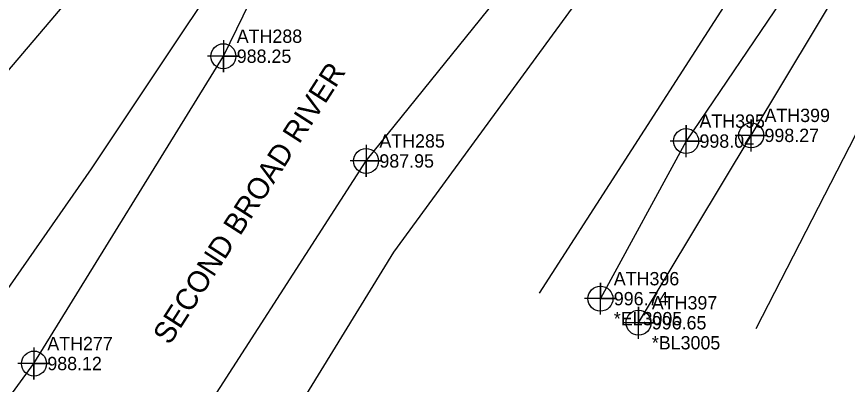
# Model space of a CAD drawing. Extents: x 1116345 to 1117546, y 660629 to 661859.
# Drawn here: x 1116970 to 1117125.8, y 661227.1 to 661296.1 of the extents above; entities that cross this region are included whole.
import ezdxf

# ---------------------------------------------------------------- set-up
doc = ezdxf.new("R2010")
doc.units = 0
for name, color, linetype in [('Exist DTM Drainline Cogo Elevation', 7, 'Continuous'), ('Exist DTM Drainline Cogo Number', 7, 'Continuous'), ('Exist DTM Drainline Cogo Point CELL', 7, 'Continuous'), ('Exist DTM Drainline Text', 7, 'Continuous'), ('Exist Horizontal Alignment', 7, 'Continuous'), ('Exist Hydro Jurisdictional Stream or Body of Water', 7, 'Continuous'), ('Exist Right of Way Line', 7, 'Continuous'), ('Exist Roads EOP', 7, 'Continuous'), ('Exist Roads Soil', 7, 'Continuous'), ('Exist Roads Soil Cogo Comment', 7, 'Continuous'), ('Exist Roads Soil Cogo Elevation', 7, 'Continuous'), ('Exist Roads Soil Cogo Number', 7, 'Continuous'), ('Exist Roads Soil Cogo Point CELL', 7, 'Continuous'), ('Exist Vegetation Woods Line', 7, 'Continuous')]:
    doc.layers.add(name, color=color, linetype=linetype)

msp = doc.modelspace()

# ---------------------------------------------------------------- linework, layer by layer
at = {"layer": 'Exist DTM Drainline Cogo Point CELL'}
for points in [[(1117008.81, 661291.68), (1117008.81, 661285.68), (1117008.81, 661288.68), (1117011.81, 661288.68), (1117005.81, 661288.68)], [(1117035.55, 661272.03), (1117035.55, 661266.03), (1117035.55, 661269.03), (1117038.55, 661269.03), (1117032.55, 661269.03)], [(1116973.3, 661234.02), (1116973.3, 661228.02), (1116973.3, 661231.02), (1116976.3, 661231.02), (1116970.3, 661231.02)]]:
    msp.add_lwpolyline(points, dxfattribs=at)
for centre in [(1117008.81, 661288.68), (1117035.55, 661269.03), (1116973.3, 661231.02)]:
    msp.add_circle(centre, 2.34, dxfattribs=at)
at = {"layer": 'Exist Horizontal Alignment'}
msp.add_arc((1117130.39, 661117.25), 266.49, 124.8653, 140.6333, dxfattribs=at)
at = {"layer": 'Exist Hydro Jurisdictional Stream or Body of Water'}
for points in [[(1116999.25, 661212.66), (1117035.55, 661269.03), (1117067.84, 661309.06), (1117080.47, 661351.77), (1117079.75, 661359.69)], [(1116885.26, 661065.08), (1116909.52, 661128.83), (1116941.43, 661187.26), (1116973.3, 661231.02), (1117008.81, 661288.68), (1117028.62, 661329.39), (1117037.26, 661346.04)]]:
    msp.add_lwpolyline(points, dxfattribs=at)
at = {"layer": 'Exist Right of Way Line'}
msp.add_arc((1117130.39, 661117.25), 250.49, 124.8653, 140.6333, dxfattribs=at)
at = {"layer": 'Exist Roads EOP'}
msp.add_spline([(1117018.01, 661346.19), (1116990.86, 661332.64), (1116967.62, 661314.64), (1116940.1, 661287.74), (1116924.9, 661271.68)], degree=3, dxfattribs=at)
at = {"layer": 'Exist Roads Soil'}
for points in [[(1117086.62, 661238.67), (1117107.74, 661273.83), (1117132.45, 661314.97), (1117148.91, 661339.08), (1117168.41, 661383.47)], [(1117136.15, 661374.23), (1117145.4, 661365.55), (1117144.42, 661353.97), (1117129.29, 661327.4), (1117114.6, 661300.97), (1117095.55, 661272.76), (1117079.49, 661243.19)]]:
    msp.add_lwpolyline(points, dxfattribs=at)
at = {"layer": 'Exist Roads Soil Cogo Point CELL'}
for points in [[(1117107.74, 661270.83), (1117107.74, 661276.83), (1117107.74, 661273.83), (1117110.74, 661273.83), (1117104.74, 661273.83)], [(1117095.55, 661269.76), (1117095.55, 661275.76), (1117095.55, 661272.76), (1117098.55, 661272.76), (1117092.55, 661272.76)], [(1117079.49, 661240.19), (1117079.49, 661246.19), (1117079.49, 661243.19), (1117082.49, 661243.19), (1117076.49, 661243.19)], [(1117086.62, 661235.67), (1117086.62, 661241.67), (1117086.62, 661238.67), (1117089.62, 661238.67), (1117083.62, 661238.67)]]:
    msp.add_lwpolyline(points, dxfattribs=at)
for centre in [(1117107.74, 661273.83), (1117095.55, 661272.76), (1117079.49, 661243.19), (1117086.62, 661238.67)]:
    msp.add_circle(centre, 2.34, dxfattribs=at)
at = {"layer": 'Exist Vegetation Woods Line'}
for points in [[(1117108.68, 661237.57), (1117176.43, 661369.6), (1117213.82, 661377.08), (1117252.97, 661424.61), (1117293.44, 661481.82), (1117329.7, 661550.06), (1117355.66, 661619.6), (1117385.32, 661697.05)], [(1117100.38, 661351.82), (1117134.85, 661361.45), (1117116.32, 661319.34), (1117068.02, 661244.2)], [(1116995.5, 661178.21), (1117040.75, 661251.89), (1117075.44, 661299.42), (1117090.71, 661335.76)], [(1116822.09, 661078.95), (1116804.85, 661104.09), (1116828.12, 661132.83), (1116873.08, 661177.67), (1116894.77, 661200.05), (1116929.53, 661240.14), (1116982.13, 661302.16), (1117021.34, 661323.58), (1116984, 661267.54), (1116931.65, 661192.36), (1116900.73, 661130.25), (1116872.65, 661055.8), (1116879.08, 661003.69), (1116904.15, 660970.25)]]:
    msp.add_lwpolyline(points, dxfattribs=at)

# ---------------------------------------------------------------- texts
at = {"layer": 'Exist DTM Drainline Cogo Elevation'}
for s, p in [('988.25', (1117011.31, 661287.43)), ('987.95', (1117038.05, 661267.78)), ('988.12', (1116975.8, 661229.77))]:
    msp.add_text(s, height=2.5, dxfattribs=at).set_placement(p)
at = {"layer": 'Exist DTM Drainline Cogo Number'}
for s, p in [('ATH288', (1117011.31, 661291.18)), ('ATH285', (1117038.05, 661271.53)), ('ATH277', (1116975.8, 661233.52))]:
    msp.add_text(s, height=2.5, dxfattribs=at).set_placement(p)
at = {"layer": 'Exist DTM Drainline Text'}
msp.add_text('SECOND BROAD RIVER', height=4, rotation=57.218, dxfattribs=at).set_placement((1116998.72, 661234.33))
at = {"layer": 'Exist Roads Soil Cogo Comment'}
for s, p in [('*EL3005', (1117081.99, 661238.19)), ('*BL3005', (1117089.12, 661233.67))]:
    msp.add_text(s, height=2.5, dxfattribs=at).set_placement(p)
at = {"layer": 'Exist Roads Soil Cogo Elevation'}
for s, p in [('998.04', (1117098.05, 661271.51)), ('998.27', (1117110.24, 661272.58)), ('996.74', (1117081.99, 661241.94)), ('996.65', (1117089.12, 661237.42))]:
    msp.add_text(s, height=2.5, dxfattribs=at).set_placement(p)
at = {"layer": 'Exist Roads Soil Cogo Number'}
for s, p in [('ATH399', (1117110.24, 661276.33)), ('ATH395', (1117098.05, 661275.26)), ('ATH396', (1117081.99, 661245.69)), ('ATH397', (1117089.12, 661241.17))]:
    msp.add_text(s, height=2.5, dxfattribs=at).set_placement(p)

doc.saveas('drawing.dxf')
